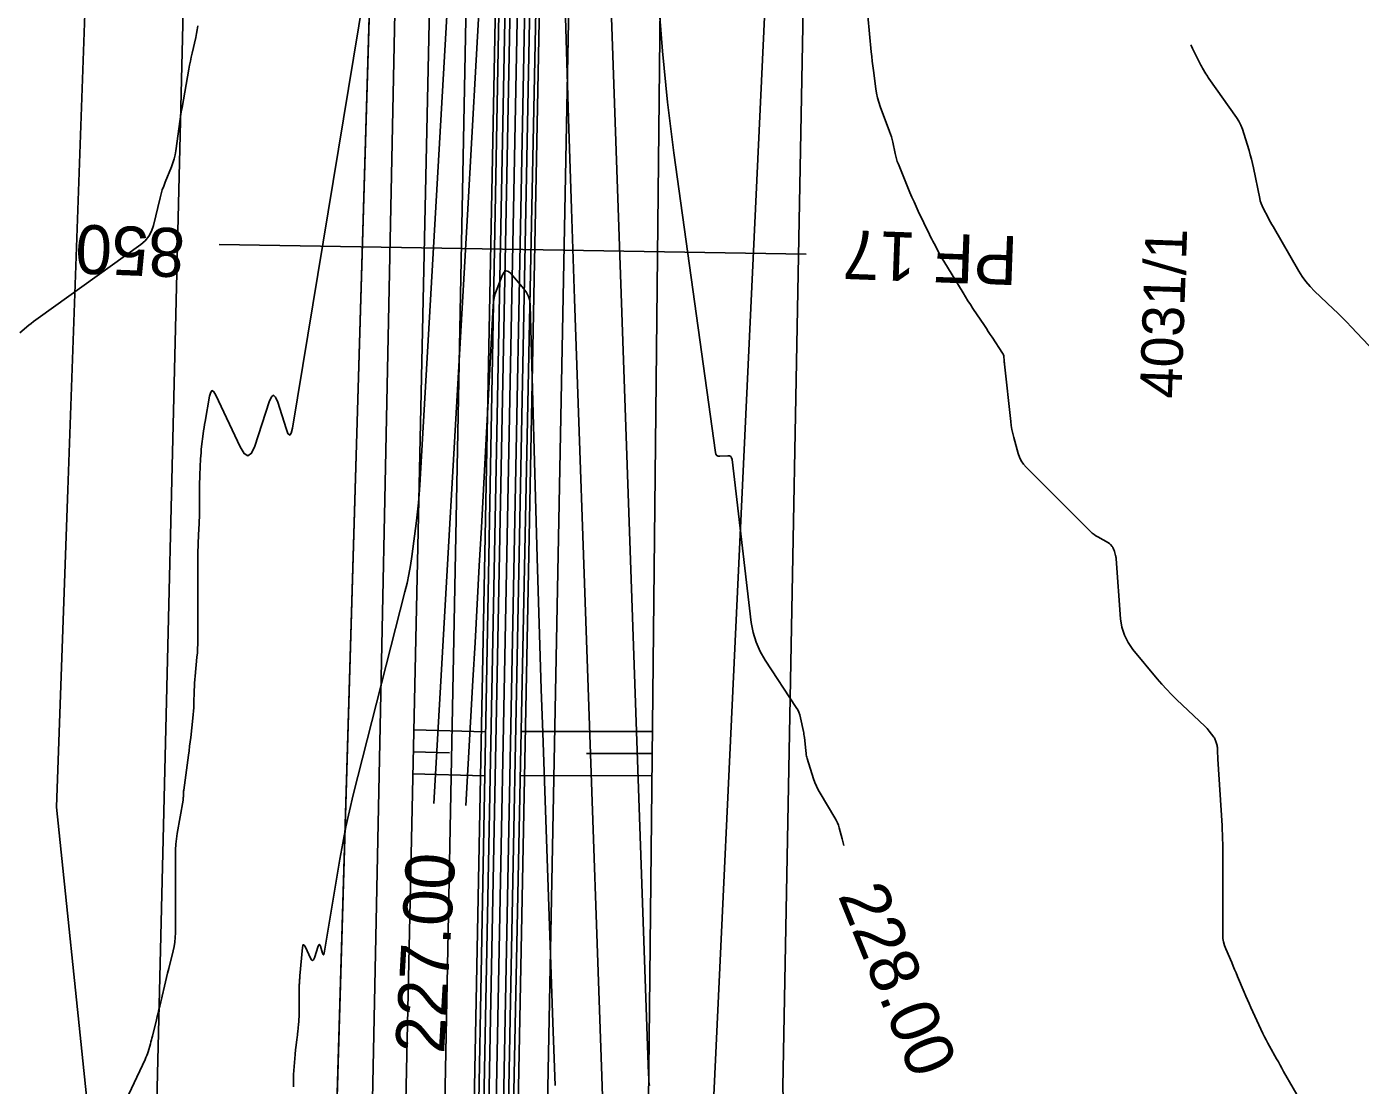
# Model space of a CAD drawing. Extents: x -534410 to -534262, y -1190162 to -1189584.
# Drawn here: x -534375.88 to -534348.62, y -1189747.77 to -1189726.14 of the extents above; entities that cross this region are included whole.
import ezdxf

# ---------------------------------------------------------------- set-up
doc = ezdxf.new("R2010")
doc.units = 0
for name, color, linetype in [('30', 7, 'Continuous'), ('31', 7, 'Continuous'), ('40', 7, 'Continuous'), ('_linie', 7, 'Continuous'), ('_N_osa', 7, 'Continuous'), ('_N_tenká', 7, 'Continuous'), ('_N_tenká_velmi', 7, 'Continuous'), ('_N_text', 7, 'Continuous'), ('_tenka', 7, 'Continuous'), ('_velmi_tenka', 7, 'Continuous'), ('Default', 7, 'Continuous'), ('Hranice parcel', 7, 'Continuous'), ('Parcelní čísla', 7, 'Continuous')]:
    doc.layers.add(name, color=color, linetype=linetype)

msp = doc.modelspace()

# ---------------------------------------------------------------- linework, layer by layer
at = {"layer": '30'}
for points in [[(-534364.91, -1189724.332), (-534364.858, -1189726.175), (-534364.802, -1189728.017), (-534364.743, -1189729.859), (-534364.68, -1189731.701), (-534364.125, -1189747.582), (-534364.096, -1189748.404)], [(-534367.558, -1189742.014), (-534366.869, -1189729.985), (-534366.779, -1189728.404), (-534366.691, -1189726.823), (-534366.604, -1189725.242)], [(-534368.987, -1189725.497), (-534370.447, -1189734.343), (-534370.473, -1189734.449), (-534370.503, -1189734.485), (-534370.538, -1189734.453), (-534370.578, -1189734.352), (-534370.748, -1189733.809), (-534370.791, -1189733.707), (-534370.834, -1189733.672), (-534370.877, -1189733.706), (-534370.921, -1189733.807), (-534371.216, -1189734.708), (-534371.283, -1189734.855), (-534371.356, -1189734.908), (-534371.434, -1189734.864), (-534371.518, -1189734.726), (-534372.01, -1189733.671), (-534372.053, -1189733.598), (-534372.089, -1189733.576), (-534372.118, -1189733.606), (-534372.141, -1189733.688), (-534372.233, -1189734.205), (-534372.244, -1189734.269), (-534372.254, -1189734.332), (-534372.263, -1189734.396), (-534372.271, -1189734.46), (-534372.303, -1189734.716), (-534372.31, -1189734.781), (-534372.316, -1189734.845), (-534372.321, -1189734.909), (-534372.325, -1189734.973), (-534372.34, -1189735.297), (-534372.343, -1189735.373), (-534372.345, -1189735.448), (-534372.347, -1189735.524), (-534372.348, -1189735.599), (-534372.349, -1189736.086), (-534372.35, -1189736.162), (-534372.352, -1189736.237), (-534372.354, -1189736.313), (-534372.358, -1189736.389), (-534372.373, -1189736.693), (-534372.377, -1189736.769), (-534372.379, -1189736.845), (-534372.381, -1189736.92), (-534372.381, -1189736.996), (-534372.381, -1189738.667), (-534372.382, -1189738.756), (-534372.386, -1189738.844), (-534372.391, -1189738.933), (-534372.399, -1189739.021), (-534372.437, -1189739.41), (-534372.443, -1189739.481), (-534372.448, -1189739.553), (-534372.452, -1189739.624), (-534372.454, -1189739.695), (-534372.46, -1189739.981), (-534372.463, -1189740.053), (-534372.467, -1189740.124), (-534372.473, -1189740.195), (-534372.48, -1189740.266), (-534372.527, -1189740.664), (-534372.537, -1189740.754), (-534372.549, -1189740.844), (-534372.56, -1189740.934), (-534372.572, -1189741.024), (-534372.669, -1189741.742), (-534372.671, -1189741.759), (-534372.673, -1189741.775), (-534372.674, -1189741.792), (-534372.675, -1189741.809), (-534372.677, -1189741.876), (-534372.678, -1189741.893), (-534372.679, -1189741.91), (-534372.681, -1189741.926), (-534372.684, -1189741.943), (-534372.801, -1189742.622), (-534372.818, -1189742.733), (-534372.83, -1189742.845), (-534372.837, -1189742.958), (-534372.839, -1189743.07), (-534372.839, -1189744.658), (-534372.842, -1189744.751), (-534372.851, -1189744.843), (-534372.865, -1189744.934), (-534372.885, -1189745.025), (-534372.976, -1189745.386), (-534372.999, -1189745.476), (-534373.021, -1189745.566), (-534373.043, -1189745.657), (-534373.064, -1189745.747), (-534373.16, -1189746.155), (-534373.176, -1189746.224), (-534373.192, -1189746.293), (-534373.209, -1189746.362), (-534373.226, -1189746.431), (-534373.307, -1189746.763), (-534373.318, -1189746.804), (-534373.328, -1189746.844), (-534373.339, -1189746.884), (-534373.351, -1189746.925), (-534373.399, -1189747.085), (-534373.412, -1189747.124), (-534373.426, -1189747.164), (-534373.441, -1189747.202), (-534373.458, -1189747.24), (-534374.015, -1189748.431)], [(-534359.176, -1189742.869), (-534359.182, -1189742.845), (-534359.196, -1189742.789), (-534359.21, -1189742.734), (-534359.27, -1189742.512), (-534359.286, -1189742.457), (-534359.307, -1189742.404), (-534359.331, -1189742.352), (-534359.358, -1189742.302), (-534359.66, -1189741.8), (-534359.699, -1189741.73), (-534359.735, -1189741.657), (-534359.766, -1189741.583), (-534359.793, -1189741.507), (-534359.927, -1189741.092), (-534359.934, -1189741.068), (-534359.94, -1189741.044), (-534359.945, -1189741.019), (-534359.948, -1189740.994), (-534359.961, -1189740.869), (-534359.968, -1189740.795), (-534359.982, -1189740.661), (-534359.985, -1189740.63), (-534359.99, -1189740.6), (-534359.995, -1189740.569), (-534360.001, -1189740.539), (-534360.058, -1189740.259), (-534360.073, -1189740.203), (-534360.092, -1189740.149), (-534360.116, -1189740.098), (-534360.146, -1189740.048), (-534360.783, -1189739.087), (-534360.888, -1189738.906), (-534360.97, -1189738.717), (-534361.029, -1189738.52), (-534361.066, -1189738.314), (-534361.459, -1189734.981), (-534361.468, -1189734.947), (-534361.486, -1189734.923), (-534361.513, -1189734.91), (-534361.548, -1189734.907), (-534361.708, -1189734.918), (-534361.744, -1189734.915), (-534361.771, -1189734.902), (-534361.789, -1189734.878), (-534361.799, -1189734.844), (-534362.651, -1189728.716), (-534362.781, -1189727.68), (-534362.885, -1189726.642), (-534362.961, -1189725.602)], [(-534348.323, -1189732.778), (-534348.801, -1189732.273), (-534348.892, -1189732.179), (-534348.984, -1189732.085), (-534349.077, -1189731.993), (-534349.172, -1189731.902), (-534349.553, -1189731.542), (-534349.644, -1189731.448), (-534349.728, -1189731.349), (-534349.805, -1189731.245), (-534349.875, -1189731.134), (-534350.4, -1189730.226), (-534350.427, -1189730.18), (-534350.453, -1189730.133), (-534350.479, -1189730.086), (-534350.503, -1189730.038), (-534350.602, -1189729.848), (-534350.625, -1189729.8), (-534350.644, -1189729.75), (-534350.66, -1189729.699), (-534350.673, -1189729.648), (-534350.801, -1189729.023), (-534350.82, -1189728.934), (-534350.842, -1189728.845), (-534350.865, -1189728.758), (-534350.89, -1189728.67), (-534350.994, -1189728.322), (-534351.023, -1189728.236), (-534351.059, -1189728.154), (-534351.101, -1189728.074), (-534351.15, -1189727.998), (-534351.71, -1189727.201), (-534351.727, -1189727.178), (-534351.742, -1189727.154), (-534351.757, -1189727.13), (-534351.772, -1189727.106), (-534351.841, -1189726.987), (-534351.849, -1189726.973), (-534351.857, -1189726.959), (-534351.865, -1189726.945), (-534351.873, -1189726.93), (-534351.904, -1189726.873), (-534351.911, -1189726.859), (-534351.919, -1189726.844), (-534351.926, -1189726.83), (-534351.933, -1189726.815), (-534352.048, -1189726.584), (-534352.069, -1189726.54), (-534352.084, -1189726.51)]]:
    msp.add_lwpolyline(points, dxfattribs=at)
at = {"layer": '31'}
for points in [[(-534364.841, -1189694.956), (-534364.38, -1189711.668), (-534364.3, -1189714.46), (-534364.216, -1189717.252), (-534364.126, -1189720.044), (-534364.031, -1189722.836), (-534363.168, -1189747.541), (-534363.164, -1189747.619), (-534363.158, -1189747.696), (-534363.15, -1189747.773)], [(-534370.428, -1189747.799), (-534370.428, -1189747.571), (-534370.428, -1189747.558), (-534370.427, -1189747.546), (-534370.392, -1189747.142), (-534370.388, -1189747.107), (-534370.385, -1189747.072), (-534370.381, -1189747.036), (-534370.377, -1189747.001), (-534370.357, -1189746.837), (-534370.351, -1189746.79), (-534370.345, -1189746.742), (-534370.334, -1189746.647), (-534370.331, -1189746.623), (-534370.329, -1189746.599), (-534370.327, -1189746.575), (-534370.325, -1189746.551), (-534370.312, -1189746.345), (-534370.31, -1189746.303), (-534370.308, -1189746.26), (-534370.307, -1189746.218), (-534370.307, -1189746.175), (-534370.307, -1189745.771), (-534370.307, -1189745.751), (-534370.306, -1189745.731), (-534370.306, -1189745.711), (-534370.305, -1189745.691), (-534370.301, -1189745.61), (-534370.299, -1189745.59), (-534370.298, -1189745.57), (-534370.297, -1189745.55), (-534370.295, -1189745.53), (-534370.244, -1189744.957), (-534370.236, -1189744.912), (-534370.223, -1189744.895), (-534370.205, -1189744.906), (-534370.183, -1189744.946), (-534370.078, -1189745.17), (-534370.056, -1189745.207), (-534370.035, -1189745.218), (-534370.016, -1189745.204), (-534369.998, -1189745.165), (-534369.92, -1189744.927), (-534369.909, -1189744.9), (-534369.897, -1189744.891), (-534369.886, -1189744.9), (-534369.874, -1189744.927), (-534369.83, -1189745.071), (-534369.819, -1189745.098), (-534369.81, -1189745.106), (-534369.802, -1189745.097), (-534369.795, -1189745.069), (-534369.478, -1189743.152), (-534369.42, -1189742.821), (-534369.355, -1189742.491), (-534369.282, -1189742.163), (-534369.203, -1189741.837), (-534368.147, -1189737.689), (-534368.104, -1189737.51), (-534368.066, -1189737.331), (-534368.034, -1189737.15), (-534368.007, -1189736.968), (-534367.911, -1189736.238), (-534367.888, -1189736.055), (-534367.869, -1189735.872), (-534367.854, -1189735.689), (-534367.841, -1189735.505), (-534366.993, -1189720.703)], [(-534358.686, -1189725.922), (-534358.615, -1189726.656), (-534358.605, -1189726.75), (-534358.595, -1189726.844), (-534358.583, -1189726.938), (-534358.571, -1189727.033), (-534358.52, -1189727.409), (-534358.505, -1189727.502), (-534358.485, -1189727.594), (-534358.459, -1189727.685), (-534358.429, -1189727.774), (-534358.239, -1189728.281), (-534358.22, -1189728.335), (-534358.202, -1189728.391), (-534358.187, -1189728.447), (-534358.175, -1189728.503), (-534358.128, -1189728.731), (-534358.114, -1189728.787), (-534358.099, -1189728.843), (-534358.081, -1189728.898), (-534358.06, -1189728.952), (-534357.823, -1189729.528), (-534357.782, -1189729.625), (-534357.74, -1189729.721), (-534357.697, -1189729.817), (-534357.652, -1189729.912), (-534357.424, -1189730.388), (-534357.401, -1189730.434), (-534357.378, -1189730.48), (-534357.355, -1189730.526), (-534357.331, -1189730.571), (-534357.235, -1189730.753), (-534357.211, -1189730.799), (-534357.186, -1189730.844), (-534357.16, -1189730.888), (-534357.133, -1189730.932), (-534356.738, -1189731.581), (-534356.689, -1189731.661), (-534356.638, -1189731.74), (-534356.587, -1189731.819), (-534356.535, -1189731.898), (-534356.3, -1189732.248), (-534356.261, -1189732.307), (-534356.221, -1189732.367), (-534356.182, -1189732.427), (-534356.142, -1189732.486), (-534355.928, -1189732.813), (-534355.918, -1189732.829), (-534355.911, -1189732.846), (-534355.906, -1189732.864), (-534355.904, -1189732.882), (-534355.898, -1189732.958), (-534355.896, -1189732.977), (-534355.895, -1189732.996), (-534355.893, -1189733.015), (-534355.891, -1189733.034), (-534355.761, -1189734.206), (-534355.751, -1189734.289), (-534355.737, -1189734.372), (-534355.72, -1189734.453), (-534355.699, -1189734.534), (-534355.612, -1189734.858), (-534355.585, -1189734.936), (-534355.549, -1189735.009), (-534355.504, -1189735.076), (-534355.45, -1189735.138), (-534354.128, -1189736.459), (-534354.095, -1189736.49), (-534354.06, -1189736.519), (-534354.023, -1189736.544), (-534353.984, -1189736.567), (-534353.766, -1189736.685), (-534353.755, -1189736.691), (-534353.745, -1189736.699), (-534353.735, -1189736.707), (-534353.726, -1189736.717), (-534353.687, -1189736.762), (-534353.681, -1189736.769), (-534353.676, -1189736.777), (-534353.672, -1189736.785), (-534353.668, -1189736.793), (-534353.653, -1189736.827), (-534353.65, -1189736.836), (-534353.646, -1189736.845), (-534353.644, -1189736.854), (-534353.641, -1189736.862), (-534353.62, -1189736.943), (-534353.616, -1189736.96), (-534353.613, -1189736.977), (-534353.61, -1189736.993), (-534353.609, -1189737.01), (-534353.517, -1189738.238), (-534353.491, -1189738.41), (-534353.44, -1189738.572), (-534353.365, -1189738.724), (-534353.264, -1189738.865), (-534352.768, -1189739.462), (-534352.674, -1189739.572), (-534352.577, -1189739.679), (-534352.477, -1189739.783), (-534352.374, -1189739.884), (-534351.79, -1189740.436), (-534351.767, -1189740.459), (-534351.745, -1189740.483), (-534351.724, -1189740.507), (-534351.704, -1189740.533), (-534351.612, -1189740.656), (-534351.6, -1189740.673), (-534351.59, -1189740.69), (-534351.582, -1189740.709), (-534351.575, -1189740.728), (-534351.551, -1189740.806), (-534351.545, -1189740.825), (-534351.541, -1189740.845), (-534351.538, -1189740.865), (-534351.537, -1189740.885), (-534351.533, -1189741.003), (-534351.532, -1189741.03), (-534351.531, -1189741.056), (-534351.53, -1189741.083), (-534351.528, -1189741.109), (-534351.443, -1189742.463), (-534351.44, -1189742.501), (-534351.438, -1189742.539), (-534351.437, -1189742.577), (-534351.435, -1189742.615), (-534351.431, -1189742.768), (-534351.43, -1189742.806), (-534351.429, -1189742.845), (-534351.428, -1189742.883), (-534351.428, -1189742.921), (-534351.428, -1189744.692), (-534351.424, -1189744.768), (-534351.413, -1189744.841), (-534351.394, -1189744.914), (-534351.367, -1189744.984), (-534351.245, -1189745.263), (-534351.215, -1189745.333), (-534351.185, -1189745.403), (-534351.155, -1189745.473), (-534351.125, -1189745.544), (-534350.988, -1189745.869), (-534350.955, -1189745.947), (-534350.922, -1189746.024), (-534350.887, -1189746.101), (-534350.852, -1189746.177), (-534350.606, -1189746.711), (-534350.575, -1189746.777), (-534350.542, -1189746.843), (-534350.508, -1189746.908), (-534350.473, -1189746.973), (-534350.328, -1189747.229), (-534350.292, -1189747.293), (-534350.256, -1189747.357), (-534350.22, -1189747.421), (-534350.183, -1189747.485), (-534349.794, -1189748.168)], [(-534376.02, -1189732.397), (-534375.836, -1189732.242), (-534375.789, -1189732.203), (-534375.742, -1189732.166), (-534375.694, -1189732.13), (-534375.645, -1189732.094), (-534373.547, -1189730.591), (-534373.455, -1189730.513), (-534373.381, -1189730.422), (-534373.325, -1189730.318), (-534373.287, -1189730.203), (-534373.153, -1189729.64), (-534373.131, -1189729.558), (-534373.107, -1189729.476), (-534373.079, -1189729.396), (-534373.049, -1189729.317), (-534372.92, -1189729.002), (-534372.89, -1189728.923), (-534372.865, -1189728.842), (-534372.846, -1189728.76), (-534372.832, -1189728.676), (-534372.723, -1189727.883), (-534372.721, -1189727.875), (-534372.72, -1189727.867), (-534372.718, -1189727.859), (-534372.716, -1189727.852), (-534372.708, -1189727.821), (-534372.706, -1189727.813), (-534372.704, -1189727.805), (-534372.702, -1189727.797), (-534372.701, -1189727.789), (-534372.565, -1189727.007), (-534372.55, -1189726.926), (-534372.534, -1189726.845), (-534372.517, -1189726.765), (-534372.499, -1189726.684), (-534372.422, -1189726.364), (-534372.405, -1189726.283), (-534372.392, -1189726.202), (-534372.383, -1189726.121)], [(-534366.904, -1189742.051), (-534366.758, -1189739.502), (-534366.714, -1189738.72), (-534366.67, -1189737.938), (-534366.627, -1189737.155), (-534366.585, -1189736.373), (-534366.343, -1189731.843), (-534366.335, -1189731.761), (-534366.321, -1189731.68), (-534366.3, -1189731.601), (-534366.273, -1189731.523), (-534366.151, -1189731.214), (-534366.118, -1189731.154), (-534366.078, -1189731.129), (-534366.033, -1189731.14), (-534365.982, -1189731.185), (-534365.714, -1189731.495), (-534365.659, -1189731.57), (-534365.619, -1189731.651), (-534365.594, -1189731.738), (-534365.584, -1189731.831), (-534365.441, -1189736.996), (-534365.416, -1189737.889), (-534365.389, -1189738.781), (-534365.36, -1189739.674), (-534365.33, -1189740.566), (-534365.123, -1189746.489), (-534365.076, -1189747.773)]]:
    msp.add_lwpolyline(points, dxfattribs=at)
at = {"layer": '_linie'}
for points in [[(-534366.12, -1189620.81), (-534364.52, -1189627.2), (-534365.69, -1189653.8), (-534366.76, -1189684.81), (-534368.14, -1189748.73), (-534368.38, -1189779.14), (-534368.65, -1189820.64), (-534368.59, -1189847.58), (-534367.2, -1189913.8)], [(-534363.12, -1189621.02), (-534362.79, -1189621.58), (-534361.82, -1189627.79), (-534363.46, -1189653.55), (-534365.47, -1189684.77), (-534366.65, -1189748.83), (-534366.75, -1189779.47), (-534366.9, -1189820.47), (-534366.95, -1189846.72), (-534366.338, -1189888.804), (-534363.85, -1189911.95), (-534357.07, -1189929.19), (-534352.334, -1189940.856)], [(-534359.03, -1189621.26), (-534359.41, -1189621.83), (-534360.84, -1189627.76), (-534362.92, -1189653.56), (-534364.64, -1189685), (-534365.94, -1189748.9), (-534366.02, -1189779.52), (-534366.03, -1189820.5), (-534366.48, -1189846.73), (-534365.511, -1189888.873), (-534362.72, -1189912.12), (-534356.62, -1189928.64), (-534351.589, -1189940.594)]]:
    msp.add_lwpolyline(points, dxfattribs=at)
at = {"layer": '_N_osa'}
msp.add_lwpolyline([(-534351.95, -1189940.722), (-534356.845, -1189928.915), (-534363.285, -1189912.035), (-534365.925, -1189888.838), (-534366.715, -1189846.725), (-534366.465, -1189820.485), (-534366.385, -1189779.495), (-534366.295, -1189748.865), (-534365.055, -1189684.885), (-534363.19, -1189653.555), (-534361.333, -1189627.822)], dxfattribs=at)
at = {"layer": '_N_tenká'}
for points in [[(-534352.92, -1189941.124), (-534357.821, -1189929.303), (-534364.313, -1189912.285), (-534366.973, -1189888.908), (-534367.765, -1189846.73), (-534367.515, -1189820.479), (-534367.435, -1189779.492), (-534367.345, -1189748.853), (-534366.104, -1189684.844), (-534364.238, -1189653.486), (-534362.424, -1189628.352), (-534361.782, -1189627.792)], [(-534352.089, -1189940.779), (-534356.984, -1189928.97), (-534363.432, -1189912.071), (-534366.074, -1189888.848), (-534366.865, -1189846.726), (-534366.615, -1189820.484), (-534366.535, -1189779.495), (-534366.445, -1189748.863), (-534365.205, -1189684.879), (-534363.34, -1189653.545), (-534361.483, -1189627.812)], [(-534351.812, -1189940.664), (-534356.706, -1189928.86), (-534363.138, -1189911.999), (-534365.775, -1189888.828), (-534366.565, -1189846.724), (-534366.315, -1189820.486), (-534366.235, -1189779.495), (-534366.145, -1189748.867), (-534364.905, -1189684.891), (-534363.04, -1189653.565), (-534361.184, -1189627.831)], [(-534350.98, -1189940.319), (-534355.869, -1189928.527), (-534362.257, -1189911.785), (-534364.876, -1189888.769), (-534365.665, -1189846.72), (-534365.415, -1189820.491), (-534365.335, -1189779.498), (-534365.245, -1189748.877), (-534364.006, -1189684.926), (-534362.142, -1189653.624), (-534360.329, -1189628.488), (-534360.884, -1189627.851)]]:
    msp.add_lwpolyline(points, dxfattribs=at)
at = {"layer": '_N_tenká_velmi'}
for points in [[(-534352.366, -1189940.894), (-534357.263, -1189929.081), (-534363.726, -1189912.142), (-534366.374, -1189888.868), (-534367.165, -1189846.727), (-534366.915, -1189820.482), (-534366.835, -1189779.494), (-534366.745, -1189748.86), (-534365.505, -1189684.867), (-534363.639, -1189653.525), (-534361.782, -1189627.792)], [(-534352.181, -1189940.817), (-534357.077, -1189929.007), (-534363.53, -1189912.095), (-534366.174, -1189888.855), (-534366.965, -1189846.726), (-534366.715, -1189820.484), (-534366.635, -1189779.494), (-534366.545, -1189748.862), (-534365.305, -1189684.875), (-534363.439, -1189653.539), (-534361.583, -1189627.805)], [(-534351.719, -1189940.626), (-534356.613, -1189928.823), (-534363.04, -1189911.975), (-534365.675, -1189888.822), (-534366.465, -1189846.724), (-534366.215, -1189820.486), (-534366.135, -1189779.496), (-534366.045, -1189748.868), (-534364.805, -1189684.895), (-534362.941, -1189653.571), (-534361.084, -1189627.838)], [(-534351.534, -1189940.549), (-534356.427, -1189928.749), (-534362.844, -1189911.928), (-534365.475, -1189888.808), (-534366.265, -1189846.723), (-534366.015, -1189820.488), (-534365.935, -1189779.496), (-534365.845, -1189748.87), (-534364.605, -1189684.903), (-534362.741, -1189653.585), (-534360.884, -1189627.851)]]:
    msp.add_lwpolyline(points, dxfattribs=at)
at = {"layer": '_N_text'}
msp.add_lwpolyline([(-534359.944, -1189730.789), (-534371.942, -1189730.594)], dxfattribs=at)
at = {"layer": '_tenka'}
for points in [[(-534349.13, -1189939.73), (-534354.63, -1189926.96), (-534362.03, -1189907.65), (-534364.521, -1189888.74), (-534364.47, -1189846.64), (-534364.29, -1189820.63), (-534364.22, -1189780.69), (-534363.18, -1189749.38), (-534362.5, -1189685.39), (-534360.27, -1189651.6), (-534357.03, -1189627.34), (-534354.77, -1189620.37)], [(-534366.12, -1189620.81), (-534364.52, -1189627.2), (-534365.69, -1189653.8), (-534366.76, -1189684.81), (-534368.14, -1189748.73), (-534368.38, -1189779.14), (-534368.65, -1189820.64), (-534368.59, -1189847.58), (-534367.2, -1189913.8)], [(-534366.12, -1189620.81), (-534364.52, -1189627.2), (-534365.69, -1189653.8), (-534366.76, -1189684.81), (-534368.14, -1189748.73), (-534368.38, -1189779.14), (-534368.65, -1189820.64), (-534368.59, -1189847.58), (-534367.2, -1189913.8)], [(-534363.12, -1189621.02), (-534362.79, -1189621.58), (-534361.82, -1189627.79), (-534363.46, -1189653.55), (-534365.47, -1189684.77), (-534366.65, -1189748.83), (-534366.75, -1189779.47), (-534366.9, -1189820.47), (-534366.95, -1189846.72), (-534366.338, -1189888.804), (-534363.85, -1189911.95), (-534357.07, -1189929.19), (-534352.334, -1189940.856)], [(-534363.12, -1189621.02), (-534362.79, -1189621.58), (-534361.82, -1189627.79), (-534363.46, -1189653.55), (-534365.47, -1189684.77), (-534366.65, -1189748.83), (-534366.75, -1189779.47), (-534366.9, -1189820.47), (-534366.95, -1189846.72), (-534366.338, -1189888.804), (-534363.85, -1189911.95), (-534357.07, -1189929.19), (-534352.334, -1189940.856)], [(-534359.03, -1189621.26), (-534359.41, -1189621.83), (-534360.84, -1189627.76), (-534362.92, -1189653.56), (-534364.64, -1189685), (-534365.94, -1189748.9), (-534366.02, -1189779.52), (-534366.03, -1189820.5), (-534366.48, -1189846.73), (-534365.511, -1189888.873), (-534362.72, -1189912.12), (-534356.62, -1189928.64), (-534351.589, -1189940.594)], [(-534359.03, -1189621.26), (-534359.41, -1189621.83), (-534360.84, -1189627.76), (-534362.92, -1189653.56), (-534364.64, -1189685), (-534365.94, -1189748.9), (-534366.02, -1189779.52), (-534366.03, -1189820.5), (-534366.48, -1189846.73), (-534365.511, -1189888.873), (-534362.72, -1189912.12), (-534356.62, -1189928.64), (-534351.589, -1189940.594)], [(-534368.65, -1189626.81), (-534368.65, -1189626.81), (-534367.31, -1189654.04), (-534367.67, -1189685.23), (-534369.56, -1189748.93), (-534369.48, -1189778.6), (-534369.45, -1189820.62), (-534369.45, -1189847.87), (-534371.206, -1189896.071), (-534372.39, -1189914.47)]]:
    msp.add_lwpolyline(points, dxfattribs=at)
at = {"layer": '_velmi_tenka'}
for p, q in [((-534367.959, -1189740.505), (-534366.493, -1189740.547)), ((-534363.09, -1189740.544), (-534365.778, -1189740.54)), ((-534367.972, -1189740.954), (-534367.239, -1189740.976)), ((-534363.091, -1189740.994), (-534364.435, -1189740.992)), ((-534367.985, -1189741.404), (-534366.519, -1189741.447)), ((-534363.092, -1189741.444), (-534365.78, -1189741.44))]:
    msp.add_line(p, q, dxfattribs=at)
at = {"layer": 'Default'}
msp.add_line((-534367.67, -1189685.23), (-534369.56, -1189748.93), dxfattribs=at)
msp.add_lwpolyline([(-534349.13, -1189939.73), (-534354.63, -1189926.96), (-534362.03, -1189907.65), (-534364.521, -1189888.74), (-534364.47, -1189846.64), (-534364.29, -1189820.63), (-534364.22, -1189780.69), (-534363.18, -1189749.38), (-534362.5, -1189685.39), (-534360.27, -1189651.6), (-534357.03, -1189627.34), (-534354.77, -1189620.37)], dxfattribs=at)
at = {"layer": 'Hranice parcel'}
for p, q in [((-534371.04, -1189658.4), (-534373.49, -1189759.21)), ((-534369.14, -1189764.19), (-534367.77, -1189697.34))]:
    msp.add_line(p, q, dxfattribs=at)
for points in [[(-534373.49, -1189759.21), (-534375.27, -1189742.09), (-534373.87, -1189702.99), (-534373.87, -1189662.03), (-534374.42, -1189646.7)], [(-534359.48, -1189697.97), (-534362.6, -1189764.35), (-534362.34, -1189901.56)], [(-534359.48, -1189697.97), (-534360.42, -1189747.8), (-534359.17, -1189788.69), (-534356.86, -1189843.2), (-534358.53, -1189915.98)]]:
    msp.add_lwpolyline(points, dxfattribs=at)

# ---------------------------------------------------------------- texts
at = {"layer": '40'}
for s, rotation, p in [('227.00', 86.7381, (-534367.349, -1189747.136)), ('228.00', 292.113, (-534359.302, -1189743.889))]:
    msp.add_text(s, height=1, rotation=rotation, dxfattribs=at).set_placement(p)
at = {"layer": '_N_text'}
for s, rotation, p in [('850', 177.8451, (-534372.632, -1189730.266)), ('PF 17', 177.8926, (-534355.604, -1189730.425))]:
    msp.add_text(s, height=1, rotation=rotation, dxfattribs=at).set_placement(p)
at = {"layer": 'Parcelní čísla'}
msp.add_text('4031/1', height=0.85, rotation=88, dxfattribs=at).set_placement((-534352.276, -1189733.748))

doc.saveas('drawing.dxf')
